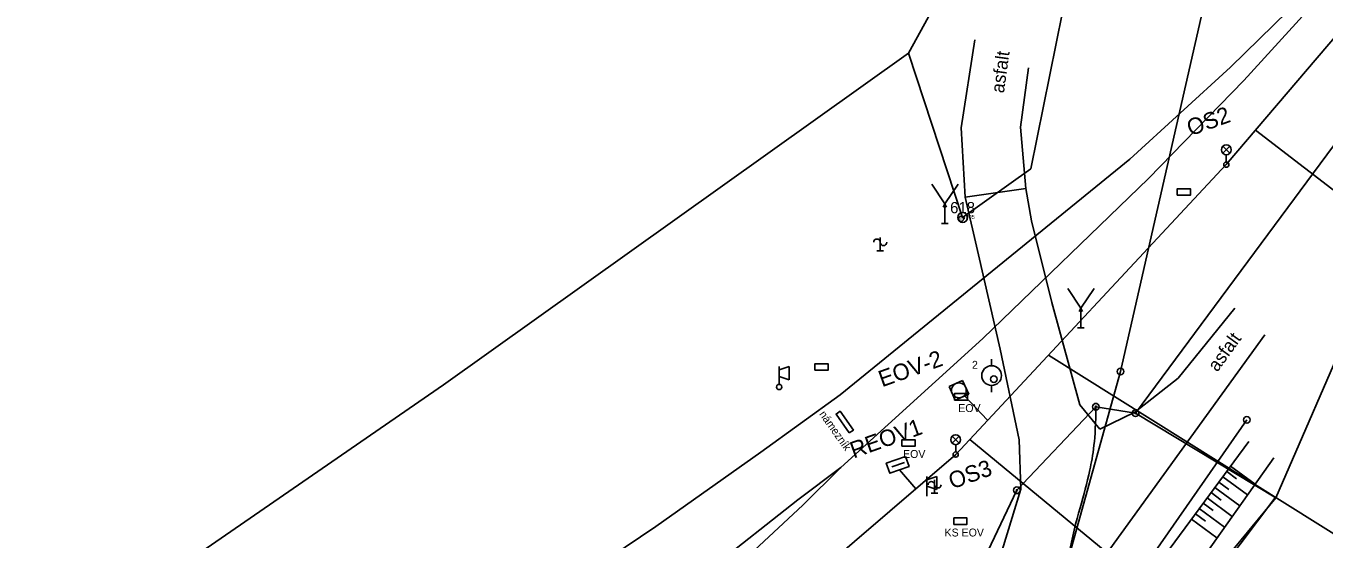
# Model space of a CAD drawing. Extents: x -734423 to 647242, y -1165906 to -111601.
# Drawn here: x -532656.7 to -532558.1, y -1114291 to -1114252 of the extents above; entities that cross this region are included whole.
import ezdxf

# ---------------------------------------------------------------- set-up
doc = ezdxf.new("R2010")
doc.units = 0
for name, color, linetype in [('Vrstva 13', 7, 'Continuous'), ('Vrstva 14', 7, 'Continuous'), ('Vrstva 15', 7, 'Continuous'), ('Vrstva 16', 7, 'Continuous'), ('Vrstva 17', 7, 'Continuous'), ('Vrstva 18', 7, 'Continuous'), ('Vrstva 2', 7, 'Continuous'), ('Vrstva 21', 7, 'Continuous'), ('Vrstva 23', 7, 'Continuous'), ('Vrstva 24', 7, 'Continuous'), ('Vrstva 26', 7, 'Continuous'), ('Vrstva 7', 7, 'Continuous'), ('Vrstva 8', 7, 'Continuous'), ('Vrstva 9', 7, 'Continuous')]:
    doc.layers.add(name, color=color, linetype=linetype)

msp = doc.modelspace()

# ---------------------------------------------------------------- linework, layer by layer
at = {"layer": 'Vrstva 13'}
msp.add_open_spline([(-532575.444, -1114280.959), (-532575.443, -1114283.433), (-532575.896, -1114285.972), (-532576.585, -1114288.447), (-532577.606, -1114292.135), (-532577.889, -1114296.195), (-532580.748, -1114298.956), (-532585.672, -1114303.695), (-532591.105, -1114306.8), (-532596.564, -1114310.307), (-532613.19, -1114320.97), (-532629.736, -1114331.763), (-532646.478, -1114342.245)], degree=3, dxfattribs=at)
at = {"layer": 'Vrstva 14'}
for p, q in [((-532530.437, -1114224.718), (-532572.425, -1114281.444)), ((-532585.273, -1114246.095), (-532589.681, -1114254.101)), ((-532577.966, -1114250.986), (-532580.376, -1114262.897)), ((-532589.681, -1114254.101), (-532624.995, -1114279.283)), ((-532589.681, -1114254.101), (-532585.56, -1114266.582)), ((-532585.56, -1114266.582), (-532580.376, -1114262.897)), ((-532561.772, -1114287.89), (-532555.044, -1114272.369)), ((-532624.995, -1114279.283), (-532673.031, -1114312.377)), ((-532575.444, -1114280.959), (-532581.442, -1114287.302)), ((-532572.425, -1114281.444), (-532575.444, -1114280.959)), ((-532561.772, -1114287.89), (-532572.425, -1114281.444)), ((-532581.442, -1114287.302), (-532584.124, -1114292.94)), ((-532573.315, -1114301.848), (-532561.772, -1114287.89))]:
    msp.add_line(p, q, dxfattribs=at)
at = {"layer": 'Vrstva 15'}
for p, q in [((-532565.21, -1114255.16), (-532559.33, -1114249.4)), ((-532558.67, -1114250.13), (-532564.19, -1114256.18)), ((-532572.85, -1114262.15), (-532565.21, -1114255.16)), ((-532564.19, -1114256.18), (-532571.44, -1114263.62)), ((-532565.794, -1114261.71), (-532565.266, -1114261.18)), ((-532565.794, -1114261.18), (-532565.266, -1114261.71)), ((-532572.85, -1114262.15), (-532594.87, -1114280.05)), ((-532565.53, -1114261.82), (-532565.53, -1114262.37)), ((-532586.91, -1114265.55), (-532587.91, -1114264.05)), ((-532585.36, -1114265.04), (-532580.75, -1114264.38)), ((-532584.03, -1114275.77), (-532571.44, -1114263.62)), ((-532587.16, -1114267.05), (-532586.66, -1114267.05)), ((-532591.829, -1114268.113), (-532591.829, -1114269.113)), ((-532591.579, -1114269.113), (-532592.079, -1114269.113)), ((-532576.58, -1114273.47), (-532577.58, -1114271.97)), ((-532576.83, -1114274.97), (-532576.33, -1114274.97)), ((-532584.03, -1114275.77), (-532594.81, -1114285.57)), ((-532599.5, -1114279.26), (-532599.5, -1114277.91)), ((-532598.75, -1114277.91), (-532599.5, -1114278.16)), ((-532598.75, -1114277.91), (-532598.75, -1114278.91)), ((-532583.36, -1114277.84), (-532583.36, -1114277.34)), ((-532598.75, -1114278.91), (-532599.5, -1114278.66)), ((-532594.87, -1114280.05), (-532600.9, -1114284.42)), ((-532583.36, -1114279.34), (-532583.36, -1114279.84)), ((-532586.354, -1114283.73), (-532585.826, -1114283.2)), ((-532586.354, -1114283.2), (-532585.826, -1114283.73)), ((-532586.09, -1114283.84), (-532586.09, -1114284.39)), ((-532608.87, -1114290.05), (-532600.9, -1114284.42)), ((-532598.08, -1114288.02), (-532594.81, -1114285.57)), ((-532597.7, -1114288.44), (-532594.81, -1114285.57)), ((-532588.27, -1114287.6), (-532588.27, -1114286.25)), ((-532587.52, -1114286.25), (-532588.27, -1114286.5)), ((-532587.52, -1114287.25), (-532588.27, -1114287)), ((-532587.699, -1114286.523), (-532587.699, -1114287.523)), ((-532587.52, -1114286.25), (-532587.52, -1114287.25)), ((-532606.02, -1114294.28), (-532598.08, -1114288.02)), ((-532588.27, -1114287.6), (-532588.27, -1114287.75)), ((-532587.449, -1114287.523), (-532587.949, -1114287.523)), ((-532561.77, -1114287.79), (-532567.01, -1114294.75)), ((-532605.12, -1114295.33), (-532597.7, -1114288.44)), ((-532614.45, -1114293.79), (-532608.87, -1114290.05))]:
    msp.add_line(p, q, dxfattribs=at)
for points in [[(-532586.91, -1114267.05), (-532586.91, -1114265.55), (-532585.91, -1114264.05)], [(-532586.786, -1114265.8), (-532586.91, -1114265.55), (-532587.034, -1114265.8)], [(-532576.58, -1114274.97), (-532576.58, -1114273.47), (-532575.58, -1114271.97)], [(-532576.456, -1114273.72), (-532576.58, -1114273.47), (-532576.704, -1114273.72)]]:
    msp.add_lwpolyline(points, dxfattribs=at)
for points in [[(-532569.26, -1114264.9), (-532568.26, -1114264.9), (-532568.26, -1114264.4), (-532569.26, -1114264.4)], [(-532596.79, -1114278.19), (-532595.79, -1114278.19), (-532595.79, -1114277.69), (-532596.79, -1114277.69)], [(-532586.19, -1114280.46), (-532585.19, -1114280.46), (-532585.19, -1114279.96), (-532586.19, -1114279.96)], [(-532594.17, -1114282.946), (-532595.177, -1114281.515), (-532594.871, -1114281.299), (-532593.863, -1114282.73)], [(-532590.18, -1114283.96), (-532589.18, -1114283.96), (-532589.18, -1114283.46), (-532590.18, -1114283.46)], [(-532586.23, -1114289.9), (-532585.23, -1114289.9), (-532585.23, -1114289.4), (-532586.23, -1114289.4)]]:
    msp.add_lwpolyline(points, close=True, dxfattribs=at)
for centre, radius in [((-532565.53, -1114261.445), 0.375), ((-532565.53, -1114262.57), 0.2), ((-532583.36, -1114278.59), 0.75), ((-532573.56, -1114278.28), 0.25), ((-532583.19, -1114278.87), 0.25), ((-532599.5, -1114279.46), 0.2), ((-532563.97, -1114281.96), 0.25), ((-532586.09, -1114283.465), 0.375), ((-532586.09, -1114284.59), 0.2)]:
    msp.add_circle(centre, radius, dxfattribs=at)
for centre, start, end in [((-532592.07, -1114268.47), 0, 180), ((-532591.57, -1114268.47), 180, 0), ((-532587.94, -1114286.88), 0, 180), ((-532587.44, -1114286.88), 180, 0)]:
    msp.add_arc(centre, 0.25, start, end, dxfattribs=at)
at = {"layer": 'Vrstva 16'}
for p, q in [((-532575.444, -1114280.959), (-532575.444, -1114280.959)), ((-532572.425, -1114281.444), (-532572.425, -1114281.444)), ((-532581.442, -1114287.302), (-532581.442, -1114287.302))]:
    msp.add_line(p, q, dxfattribs=at)
for centre, radius in [((-532575.444, -1114280.959), 0.258), ((-532575.444, -1114280.959), 0.25), ((-532575.444, -1114280.959), 0.05), ((-532575.444, -1114280.959), 0.05), ((-532572.425, -1114281.444), 0.258), ((-532572.425, -1114281.444), 0.25), ((-532572.425, -1114281.444), 0.05), ((-532572.425, -1114281.444), 0.05), ((-532581.442, -1114287.302), 0.258), ((-532581.442, -1114287.302), 0.25), ((-532581.442, -1114287.302), 0.05), ((-532581.442, -1114287.302), 0.05)]:
    msp.add_circle(centre, radius, dxfattribs=at)
at = {"layer": 'Vrstva 17'}
for centre, radius in [((-532585.556, -1114266.582), 0.375), ((-532585.56, -1114266.582), 0.0164)]:
    msp.add_circle(centre, radius, dxfattribs=at)
at = {"layer": 'Vrstva 18'}
for radius in [0.188, 0.00025]:
    msp.add_circle((-532585.68, -1114266.69), radius, dxfattribs=at)
at = {"layer": 'Vrstva 2'}
for p, q in [((-532583.662, -1114281.99), (-532585.442, -1114280.099)), ((-532590.36, -1114285.751), (-532589.122, -1114287.193))]:
    msp.add_line(p, q, dxfattribs=at)
msp.add_lwpolyline([(-532846.625, -1114416.177), (-532848.108, -1114412.135), (-532808.842, -1114398.198), (-532780.05, -1114388.6), (-532754.69, -1114379.36), (-532726.64, -1114369.2), (-532698.29, -1114356.28), (-532677.56, -1114346.43), (-532659.12, -1114337.79), (-532635.25, -1114325.58), (-532614.01, -1114308.56), (-532586.09, -1114284.59), (-532565.53, -1114262.57), (-532540.97, -1114233.76), (-532534.452, -1114225.441), (-532535.662, -1114224.613)], dxfattribs=at)
at = {"layer": 'Vrstva 21'}
for p, q in [((-532584.64, -1114253.09), (-532585.67, -1114259.77)), ((-532581.17, -1114259.72), (-532580.55, -1114255.23)), ((-532585.67, -1114259.77), (-532585.36, -1114265.04)), ((-532580.75, -1114264.38), (-532581.17, -1114259.72)), ((-532580.33, -1114266.84), (-532580.75, -1114264.38)), ((-532585.36, -1114265.04), (-532584.35, -1114269.42)), ((-532578.78, -1114273.05), (-532580.33, -1114266.84)), ((-532584.35, -1114269.42), (-532582.72, -1114276.59)), ((-532576.65, -1114280.81), (-532578.78, -1114273.05)), ((-532564.88, -1114273.46), (-532569.19, -1114278.79)), ((-532574.72, -1114292.24), (-532562.59, -1114275.5)), ((-532582.72, -1114276.59), (-532581.26, -1114283.46)), ((-532569.19, -1114278.79), (-532572.48, -1114281.38)), ((-532575.13, -1114282.65), (-532576.65, -1114280.81)), ((-532572.48, -1114281.38), (-532575.13, -1114282.65)), ((-532581.26, -1114283.46), (-532581.13, -1114287.23)), ((-532581.13, -1114287.23), (-532582.56, -1114291.84))]:
    msp.add_line(p, q, dxfattribs=at)
at = {"layer": 'Vrstva 23'}
for p, q in [((-532563.81, -1114283.59), (-532570.96, -1114293.26)), ((-532561.93, -1114284.85), (-532568.98, -1114294.78)), ((-532565.499, -1114285.875), (-532564.754, -1114286.426)), ((-532565.202, -1114285.472), (-532563.346, -1114286.844)), ((-532566.094, -1114286.679), (-532565.342, -1114287.234)), ((-532565.796, -1114286.277), (-532563.925, -1114287.66)), ((-532566.985, -1114287.885), (-532565.083, -1114289.291)), ((-532566.688, -1114287.483), (-532565.93, -1114288.043)), ((-532566.391, -1114287.081), (-532564.504, -1114288.476)), ((-532567.58, -1114288.689), (-532565.662, -1114290.107)), ((-532567.283, -1114288.287), (-532566.519, -1114288.852)), ((-532568.175, -1114289.493), (-532566.241, -1114290.922)), ((-532567.877, -1114289.091), (-532567.107, -1114289.66))]:
    msp.add_line(p, q, dxfattribs=at)
at = {"layer": 'Vrstva 24'}
msp.add_lwpolyline([(-532562.56, -1114227.88), (-532567.18, -1114250.25), (-532573.56, -1114278.28), (-532581.66, -1114307.38), (-532563.97, -1114281.96)], dxfattribs=at)
at = {"layer": 'Vrstva 7'}
for p, q in [((-532586.591, -1114279.426), (-532585.563, -1114278.965)), ((-532585.563, -1114278.965), (-532585.103, -1114279.993)), ((-532586.13, -1114280.453), (-532586.591, -1114279.426)), ((-532585.103, -1114279.993), (-532586.13, -1114280.453)), ((-532590.935, -1114285.53), (-532589.986, -1114285.195))]:
    msp.add_line(p, q, dxfattribs=at)
msp.add_lwpolyline([(-532589.892, -1114284.738), (-532591.36, -1114285.256), (-532591.094, -1114286.01), (-532589.626, -1114285.491)], close=True, dxfattribs=at)
msp.add_circle((-532585.847, -1114279.709), 0.563, dxfattribs=at)
at = {"layer": 'Vrstva 9'}
for p, q in [((-532504.513, -1114305.178), (-532563.304, -1114259.959)), ((-532523.399, -1114311.912), (-532579.037, -1114277.036)), ((-532542.286, -1114318.646), (-532585.027, -1114283.452))]:
    msp.add_line(p, q, dxfattribs=at)

# ---------------------------------------------------------------- texts
at = {"layer": 'Vrstva 17'}
msp.add_text(' 618', height=0.85, dxfattribs=at).set_placement((-532586.83, -1114266.26))
at = {"layer": 'Vrstva 18'}
msp.add_text(' 4005', height=0.3, dxfattribs=at).set_placement((-532585.68, -1114266.69))
at = {"layer": 'Vrstva 26'}
for s, height, rotation, p in [('asfalt', 1, 82.13805, (-532582.429, -1114257.176)), ('asfalt', 1, 54.07247, (-532566.217, -1114278.368)), ('námezník', 0.6, 305.13419, (-532596.481, -1114281.519))]:
    msp.add_text(s, height=height, rotation=rotation, dxfattribs=at).set_placement(p)
for s, p in [('2', (-532584.852, -1114278.075)), ('EOV', (-532585.894, -1114281.362)), ('EOV', (-532590.086, -1114284.848)), ('KS EOV', (-532586.933, -1114290.812))]:
    msp.add_text(s, height=0.6, dxfattribs=at).set_placement(p)
at = {"layer": 'Vrstva 8'}
for s, p in [('OS2', (-532568.257, -1114260.414)), ('EOV-2', (-532591.684, -1114279.484)), ('REOV1', (-532593.847, -1114284.894)), ('OS3', (-532586.36, -1114287.234))]:
    msp.add_text(s, height=1.248, rotation=19.59463, dxfattribs=at).set_placement(p)

doc.saveas('drawing.dxf')
